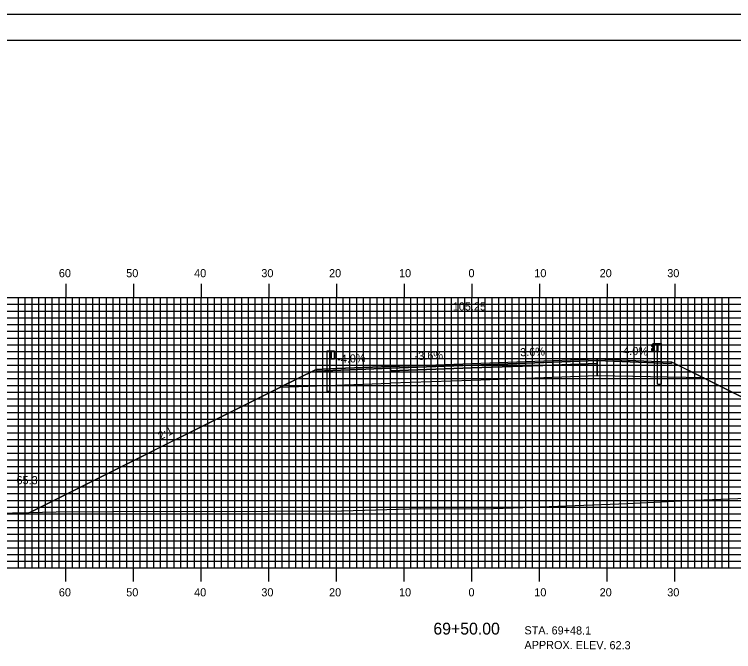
# Model space of a CAD drawing. Extents: x 1759823 to 1760167, y 442591 to 442811.
# Drawn here: x 1759921.6 to 1760027.9, y 442716.3 to 442810.5 of the extents above; entities that cross this region are included whole.
import ezdxf

# ---------------------------------------------------------------- set-up
doc = ezdxf.new("R2010")
doc.units = 0
for name, color, linetype in [('ANNOTATION', 7, 'Continuous'), ('BORDER', 7, 'Continuous'), ('BORING - NO REFUSAL', 7, 'Continuous'), ('D_Guardrail_Beam_Lt', 7, 'Continuous'), ('D_Guardrail_Beam_Rt', 7, 'Continuous'), ('D_Roadway_Centerline', 7, 'Continuous'), ('D_Roadway_Centerline_Text', 7, 'Continuous'), ('D_Roadway_Edge_Shoulder', 7, 'Continuous'), ('D_Roadway_Edge_TW', 7, 'Continuous'), ('D_Roadway_Pavement', 7, 'Continuous'), ('D_Roadway_SlopeLines', 7, 'Continuous'), ('D_Roadway_SubGrade', 7, 'Continuous'), ('D_Text_Standard', 7, 'Continuous'), ('H_V ANNOTATION', 7, 'Continuous'), ('MAJOR', 7, 'Continuous'), ('MINOR', 7, 'Continuous'), ('PLOT BOUNDARY', 7, 'Continuous'), ('S_Roadway_Centerline', 7, 'Continuous')]:
    doc.layers.add(name, color=color, linetype=linetype)

msp = doc.modelspace()

# ---------------------------------------------------------------- linework, layer by layer
at = {"layer": 'BORDER'}
msp.add_lwpolyline([(1759839.59, 442596.67), (1760159.59, 442596.67), (1760159.59, 442806.67), (1759839.59, 442806.67)], close=True, dxfattribs=at)
at = {"layer": 'D_Guardrail_Beam_Lt'}
for p, q in [((1759967.76, 442760.75), (1759967.76, 442754.75)), ((1759968.23, 442760.75), (1759967.76, 442760.75)), ((1759968.92, 442760.75), (1759968.23, 442760.75)), ((1759968.23, 442760.75), (1759968.23, 442759.58)), ((1759968.29, 442760.75), (1759968.29, 442759.58)), ((1759968.4, 442760.75), (1759968.4, 442759.58)), ((1759968.92, 442759.58), (1759968.92, 442760.75)), ((1759968.92, 442760.66), (1759968.99, 442760.65)), ((1759969.15, 442760.4), (1759968.95, 442760.26)), ((1759969.01, 442760.64), (1759969.15, 442760.54)), ((1759968.23, 442759.58), (1759968.92, 442759.58)), ((1759968.25, 442754.75), (1759968.25, 442759.58)), ((1759968.92, 442760.2), (1759968.92, 442760.13)), ((1759968.99, 442759.68), (1759968.92, 442759.66)), ((1759968.95, 442760.06), (1759969.15, 442759.93)), ((1759969.15, 442759.78), (1759969.01, 442759.68)), ((1759968.25, 442754.75), (1759967.76, 442754.75))]:
    msp.add_line(p, q, dxfattribs=at)
for centre, major_axis, start_param, end_param in [((1759968.98, 442760.61), (0.0417, 0), 0.959931, 1.376053), ((1759969.1, 442760.47), (0.0877, 0), 5.323254, 7.243116), ((1759969, 442760.2), (-0.0789, 0), 5.323254, 6.283185), ((1759969, 442760.13), (-0.0789, 0), 6.283185, 7.243116), ((1759968.98, 442759.72), (0.0417, 0), 4.907132, 5.323254), ((1759969.1, 442759.86), (0.0877, 0), 5.323254, 7.243116)]:
    msp.add_ellipse(centre, major_axis=major_axis, ratio=0.995501, start_param=start_param, end_param=end_param, dxfattribs=at)
at = {"layer": 'D_Guardrail_Beam_Rt'}
for p, q in [((1760015.92, 442761.74), (1760015.77, 442761.64)), ((1760015.77, 442761.5), (1760015.97, 442761.36)), ((1760016.01, 442761.76), (1760015.93, 442761.75)), ((1760016.01, 442761.85), (1760016.7, 442761.85)), ((1760016.01, 442760.68), (1760016.01, 442761.85)), ((1760016.53, 442761.85), (1760016.53, 442760.68)), ((1760016.63, 442761.85), (1760016.63, 442760.68)), ((1760016.7, 442761.85), (1760017.17, 442761.85)), ((1760016.7, 442761.85), (1760016.7, 442760.68)), ((1760017.17, 442761.85), (1760017.17, 442755.85)), ((1760015.97, 442761.16), (1760015.77, 442761.03)), ((1760015.77, 442760.88), (1760015.92, 442760.78)), ((1760015.93, 442760.78), (1760016.01, 442760.76)), ((1760016, 442761.3), (1760016, 442761.23)), ((1760016.7, 442760.68), (1760016.01, 442760.68)), ((1760016.67, 442755.85), (1760016.67, 442760.68)), ((1760016.67, 442755.85), (1760017.17, 442755.85))]:
    msp.add_line(p, q, dxfattribs=at)
for centre, major_axis, start_param, end_param in [((1760015.83, 442761.57), (-0.0877, 0), 5.323254, 7.243116), ((1760015.94, 442761.71), (-0.0417, 0), 4.907132, 5.323254), ((1760015.83, 442760.95), (-0.0877, 0), 5.323254, 7.243116), ((1760015.94, 442760.82), (-0.0417, 0), 0.959931, 1.376053), ((1760015.92, 442761.3), (0.0789, 0), 0, 0.959931), ((1760015.92, 442761.23), (0.0789, 0), 5.323254, 6.283185)]:
    msp.add_ellipse(centre, major_axis=major_axis, ratio=0.995501, start_param=start_param, end_param=end_param, dxfattribs=at)
at = {"layer": 'D_Roadway_Centerline'}
msp.add_lwpolyline([(1759923.86, 442736.88), (1759960.89, 442755.4), (1759966.19, 442758.04), (1759969.19, 442758.16), (1759977.19, 442758.48), (1759989.19, 442758.91), (1760001.19, 442759.35), (1760007.74, 442759.58), (1760015.74, 442759.26), (1760018.74, 442759.14), (1760023.49, 442756.77), (1760056.41, 442740.31)], dxfattribs=at)
at = {"layer": 'D_Roadway_Edge_Shoulder'}
for points in [[(1760007.74, 442759.58), (1760015.74, 442759.26), (1760015.74, 442759.26), (1760018.74, 442759.14), (1760018.74, 442758.89), (1760007.74, 442759.33)], [(1759977.19, 442758.48), (1759969.19, 442758.16), (1759969.19, 442758.16), (1759966.19, 442758.04), (1759966.19, 442757.79), (1759977.19, 442758.23)]]:
    msp.add_lwpolyline(points, close=True, dxfattribs=at)
at = {"layer": 'D_Roadway_Edge_TW'}
for points in [[(1759977.19, 442758.23), (1759977.19, 442758.48), (1759989.19, 442758.91), (1760001.19, 442759.35), (1760001.19, 442759.1), (1759989.19, 442758.66)], [(1760001.19, 442759.35), (1760007.74, 442759.58), (1760007.74, 442759.33), (1760001.19, 442759.1)]]:
    msp.add_lwpolyline(points, close=True, dxfattribs=at)
at = {"layer": 'D_Roadway_Pavement'}
for points in [[(1760001.19, 442759.1), (1760007.74, 442759.33), (1760007.74, 442758.92), (1760001.19, 442758.68)], [(1759977.19, 442757.82), (1759977.19, 442758.23), (1759989.19, 442758.66), (1760001.19, 442759.1), (1760001.19, 442758.68), (1759989.19, 442758.25)]]:
    msp.add_lwpolyline(points, close=True, dxfattribs=at)
for points in [[(1760007.74, 442759.33), (1760007.74, 442758.92)], [(1760007.74, 442759.33), (1760007.74, 442758.92)], [(1759977.19, 442758.23), (1759977.19, 442757.82)]]:
    msp.add_lwpolyline(points, dxfattribs=at)
at = {"layer": 'D_Roadway_SlopeLines'}
for points in [[(1760018.74, 442759.14), (1760056.41, 442740.31)], [(1759966.19, 442758.04), (1759923.86, 442736.88)]]:
    msp.add_lwpolyline(points, dxfattribs=at)
at = {"layer": 'D_Roadway_SubGrade'}
for points in [[(1760007.74, 442758.92), (1760007.74, 442759.33), (1760018.74, 442758.89), (1760018.74, 442759.14), (1760023.49, 442756.77), (1760007.74, 442757.08)], [(1759977.19, 442757.82), (1759977.19, 442758.23), (1759966.19, 442757.79), (1759966.19, 442758.04), (1759960.89, 442755.4), (1759977.19, 442755.98)], [(1759977.19, 442755.98), (1759977.19, 442757.82), (1759989.19, 442758.25), (1760001.19, 442758.68), (1760001.19, 442756.85), (1759989.19, 442756.41)], [(1760001.19, 442758.68), (1760007.74, 442758.92), (1760007.74, 442757.08), (1760001.19, 442756.85)]]:
    msp.add_lwpolyline(points, close=True, dxfattribs=at)
at = {"layer": 'MAJOR'}
for p, q in [((1759929.19, 442770.67), (1759929.19, 442768.67)), ((1759939.19, 442770.67), (1759939.19, 442768.67)), ((1759949.19, 442770.67), (1759949.19, 442768.67)), ((1759959.19, 442770.67), (1759959.19, 442768.67)), ((1759969.19, 442770.67), (1759969.19, 442768.67)), ((1759979.19, 442770.67), (1759979.19, 442768.67)), ((1759989.19, 442770.67), (1759989.19, 442768.67)), ((1759999.19, 442770.67), (1759999.19, 442768.67)), ((1760009.19, 442770.67), (1760009.19, 442768.67)), ((1760019.19, 442770.67), (1760019.19, 442768.67)), ((1759849.19, 442768.67), (1760129.19, 442768.67)), ((1759849.19, 442768.67), (1760129.19, 442768.67)), ((1759929.19, 442728.67), (1759929.19, 442768.67)), ((1759939.19, 442728.67), (1759939.19, 442768.67)), ((1759949.19, 442728.67), (1759949.19, 442768.67)), ((1759959.19, 442728.67), (1759959.19, 442768.67)), ((1759969.19, 442728.67), (1759969.19, 442768.67)), ((1759979.19, 442728.67), (1759979.19, 442768.67)), ((1759989.19, 442728.67), (1759989.19, 442768.67)), ((1759999.19, 442728.67), (1759999.19, 442768.67)), ((1760009.19, 442728.67), (1760009.19, 442768.67)), ((1760019.19, 442728.67), (1760019.19, 442768.67)), ((1759849.19, 442763.67), (1760129.19, 442763.67)), ((1759849.19, 442758.67), (1760129.19, 442758.67)), ((1759849.19, 442753.67), (1760129.19, 442753.67)), ((1759849.19, 442748.67), (1760129.19, 442748.67)), ((1759849.19, 442743.67), (1760129.19, 442743.67)), ((1759849.19, 442738.67), (1760129.19, 442738.67)), ((1759849.19, 442733.67), (1760129.19, 442733.67)), ((1759849.19, 442728.67), (1760129.19, 442728.67)), ((1759849.19, 442728.67), (1760129.19, 442728.67)), ((1759929.19, 442726.66), (1759929.19, 442728.67)), ((1759939.19, 442726.66), (1759939.19, 442728.67)), ((1759949.19, 442726.66), (1759949.19, 442728.67)), ((1759959.19, 442726.66), (1759959.19, 442728.67)), ((1759969.19, 442726.66), (1759969.19, 442728.67)), ((1759979.19, 442726.66), (1759979.19, 442728.67)), ((1759989.19, 442726.66), (1759989.19, 442728.67)), ((1759999.19, 442726.66), (1759999.19, 442728.67)), ((1760009.19, 442726.66), (1760009.19, 442728.67)), ((1760019.19, 442726.66), (1760019.19, 442728.67))]:
    msp.add_line(p, q, dxfattribs=at)
at = {"layer": 'MINOR'}
for p, q in [((1759922.19, 442728.67), (1759922.19, 442768.67)), ((1759923.19, 442728.67), (1759923.19, 442768.67)), ((1759924.19, 442728.67), (1759924.19, 442768.67)), ((1759925.19, 442728.67), (1759925.19, 442768.67)), ((1759926.19, 442728.67), (1759926.19, 442768.67)), ((1759927.19, 442728.67), (1759927.19, 442768.67)), ((1759928.19, 442728.67), (1759928.19, 442768.67)), ((1759930.19, 442728.67), (1759930.19, 442768.67)), ((1759931.19, 442728.67), (1759931.19, 442768.67)), ((1759932.19, 442728.67), (1759932.19, 442768.67)), ((1759933.19, 442728.67), (1759933.19, 442768.67)), ((1759934.19, 442728.67), (1759934.19, 442768.67)), ((1759935.19, 442728.67), (1759935.19, 442768.67)), ((1759936.19, 442728.67), (1759936.19, 442768.67)), ((1759937.19, 442728.67), (1759937.19, 442768.67)), ((1759938.19, 442728.67), (1759938.19, 442768.67)), ((1759940.19, 442728.67), (1759940.19, 442768.67)), ((1759941.19, 442728.67), (1759941.19, 442768.67)), ((1759942.19, 442728.67), (1759942.19, 442768.67)), ((1759943.19, 442728.67), (1759943.19, 442768.67)), ((1759944.19, 442728.67), (1759944.19, 442768.67)), ((1759945.19, 442728.67), (1759945.19, 442768.67)), ((1759946.19, 442728.67), (1759946.19, 442768.67)), ((1759947.19, 442728.67), (1759947.19, 442768.67)), ((1759948.19, 442728.67), (1759948.19, 442768.67)), ((1759950.19, 442728.67), (1759950.19, 442768.67)), ((1759951.19, 442728.67), (1759951.19, 442768.67)), ((1759952.19, 442728.67), (1759952.19, 442768.67)), ((1759953.19, 442728.67), (1759953.19, 442768.67)), ((1759954.19, 442728.67), (1759954.19, 442768.67)), ((1759955.19, 442728.67), (1759955.19, 442768.67)), ((1759956.19, 442728.67), (1759956.19, 442768.67)), ((1759957.19, 442728.67), (1759957.19, 442768.67)), ((1759958.19, 442728.67), (1759958.19, 442768.67)), ((1759960.19, 442728.67), (1759960.19, 442768.67)), ((1759961.19, 442728.67), (1759961.19, 442768.67)), ((1759962.19, 442728.67), (1759962.19, 442768.67)), ((1759963.19, 442728.67), (1759963.19, 442768.67)), ((1759964.19, 442728.67), (1759964.19, 442768.67)), ((1759965.19, 442728.67), (1759965.19, 442768.67)), ((1759966.19, 442728.67), (1759966.19, 442768.67)), ((1759967.19, 442728.67), (1759967.19, 442768.67)), ((1759968.19, 442728.67), (1759968.19, 442768.67)), ((1759970.19, 442728.67), (1759970.19, 442768.67)), ((1759971.19, 442728.67), (1759971.19, 442768.67)), ((1759972.19, 442728.67), (1759972.19, 442768.67)), ((1759973.19, 442728.67), (1759973.19, 442768.67)), ((1759974.19, 442728.67), (1759974.19, 442768.67)), ((1759975.19, 442728.67), (1759975.19, 442768.67)), ((1759976.19, 442728.67), (1759976.19, 442768.67)), ((1759977.19, 442728.67), (1759977.19, 442768.67)), ((1759978.19, 442728.67), (1759978.19, 442768.67)), ((1759980.19, 442728.67), (1759980.19, 442768.67)), ((1759981.19, 442728.67), (1759981.19, 442768.67)), ((1759982.19, 442728.67), (1759982.19, 442768.67)), ((1759983.19, 442728.67), (1759983.19, 442768.67)), ((1759984.19, 442728.67), (1759984.19, 442768.67)), ((1759985.19, 442728.67), (1759985.19, 442768.67)), ((1759986.19, 442728.67), (1759986.19, 442768.67)), ((1759987.19, 442728.67), (1759987.19, 442768.67)), ((1759988.19, 442728.67), (1759988.19, 442768.67)), ((1759990.19, 442728.67), (1759990.19, 442768.67)), ((1759991.19, 442728.67), (1759991.19, 442768.67)), ((1759992.19, 442728.67), (1759992.19, 442768.67)), ((1759993.19, 442728.67), (1759993.19, 442768.67)), ((1759994.19, 442728.67), (1759994.19, 442768.67)), ((1759995.19, 442728.67), (1759995.19, 442768.67)), ((1759996.19, 442728.67), (1759996.19, 442768.67)), ((1759997.19, 442728.67), (1759997.19, 442768.67)), ((1759998.19, 442728.67), (1759998.19, 442768.67)), ((1760000.19, 442728.67), (1760000.19, 442768.67)), ((1760001.19, 442728.67), (1760001.19, 442768.67)), ((1760002.19, 442728.67), (1760002.19, 442768.67)), ((1760003.19, 442728.67), (1760003.19, 442768.67)), ((1760004.19, 442728.67), (1760004.19, 442768.67)), ((1760005.19, 442728.67), (1760005.19, 442768.67)), ((1760006.19, 442728.67), (1760006.19, 442768.67)), ((1760007.19, 442728.67), (1760007.19, 442768.67)), ((1760008.19, 442728.67), (1760008.19, 442768.67)), ((1760010.19, 442728.67), (1760010.19, 442768.67)), ((1760011.19, 442728.67), (1760011.19, 442768.67)), ((1760012.19, 442728.67), (1760012.19, 442768.67)), ((1760013.19, 442728.67), (1760013.19, 442768.67)), ((1760014.19, 442728.67), (1760014.19, 442768.67)), ((1760015.19, 442728.67), (1760015.19, 442768.67)), ((1760016.19, 442728.67), (1760016.19, 442768.67)), ((1760017.19, 442728.67), (1760017.19, 442768.67)), ((1760018.19, 442728.67), (1760018.19, 442768.67)), ((1760020.19, 442728.67), (1760020.19, 442768.67)), ((1760021.19, 442728.67), (1760021.19, 442768.67)), ((1760022.19, 442728.67), (1760022.19, 442768.67)), ((1760023.19, 442728.67), (1760023.19, 442768.67)), ((1760024.19, 442728.67), (1760024.19, 442768.67)), ((1760025.19, 442728.67), (1760025.19, 442768.67)), ((1760026.19, 442728.67), (1760026.19, 442768.67)), ((1760027.19, 442728.67), (1760027.19, 442768.67)), ((1759849.19, 442767.67), (1760129.19, 442767.67)), ((1759849.19, 442766.67), (1760129.19, 442766.67)), ((1759849.19, 442765.67), (1760129.19, 442765.67)), ((1759849.19, 442764.67), (1760129.19, 442764.67)), ((1759849.19, 442762.67), (1760129.19, 442762.67)), ((1759849.19, 442761.67), (1760129.19, 442761.67)), ((1759849.19, 442760.67), (1760129.19, 442760.67)), ((1759849.19, 442759.67), (1760129.19, 442759.67)), ((1759849.19, 442757.67), (1760129.19, 442757.67)), ((1759849.19, 442756.67), (1760129.19, 442756.67)), ((1759849.19, 442755.67), (1760129.19, 442755.67)), ((1759849.19, 442754.67), (1760129.19, 442754.67)), ((1759849.19, 442752.67), (1760129.19, 442752.67)), ((1759849.19, 442751.67), (1760129.19, 442751.67)), ((1759849.19, 442750.67), (1760129.19, 442750.67)), ((1759849.19, 442749.67), (1760129.19, 442749.67)), ((1759849.19, 442747.67), (1760129.19, 442747.67)), ((1759849.19, 442746.67), (1760129.19, 442746.67)), ((1759849.19, 442745.67), (1760129.19, 442745.67)), ((1759849.19, 442744.67), (1760129.19, 442744.67)), ((1759849.19, 442742.67), (1760129.19, 442742.67)), ((1759849.19, 442741.67), (1760129.19, 442741.67)), ((1759849.19, 442740.67), (1760129.19, 442740.67)), ((1759849.19, 442739.67), (1760129.19, 442739.67)), ((1759849.19, 442737.67), (1760129.19, 442737.67)), ((1759849.19, 442736.67), (1760129.19, 442736.67)), ((1759849.19, 442735.67), (1760129.19, 442735.67)), ((1759849.19, 442734.67), (1760129.19, 442734.67)), ((1759849.19, 442732.67), (1760129.19, 442732.67)), ((1759849.19, 442731.67), (1760129.19, 442731.67)), ((1759849.19, 442730.67), (1760129.19, 442730.67)), ((1759849.19, 442729.67), (1760129.19, 442729.67))]:
    msp.add_line(p, q, dxfattribs=at)
at = {"layer": 'PLOT BOUNDARY'}
msp.add_lwpolyline([(1759823.4, 442590.55), (1760163.4, 442590.55), (1760163.4, 442810.55), (1759823.4, 442810.55)], close=True, dxfattribs=at)
at = {"layer": 'S_Roadway_Centerline'}
msp.add_lwpolyline([(1759849.19, 442735.32), (1759856.26, 442735.23), (1759864.27, 442735.11), (1759866.18, 442735.16), (1759884.93, 442735.84), (1759888.48, 442735.9), (1759892.58, 442735.99), (1759905.99, 442736.42), (1759911.62, 442736.59), (1759918.83, 442736.79), (1759923.72, 442736.88), (1759927.75, 442736.96), (1759944.69, 442737.06), (1759948.49, 442737.03), (1759969.96, 442737.1), (1759969.97, 442737.1), (1759969.97, 442737.1), (1759981.65, 442737.46), (1759990.98, 442737.4), (1759996.73, 442737.6), (1760012.19, 442738.19), (1760022.28, 442738.7), (1760033.54, 442739.13)], dxfattribs=at)

# ---------------------------------------------------------------- texts
at = {"layer": 'ANNOTATION'}
for s, rotation, p in [('-4.0%', 357.7094, (1760011.03, 442760.25)), ('-3.6%', 2.0618, (1759980.77, 442759.41)), ('3.6%', 2.0618, (1759996.37, 442759.97)), ('-4.0%', 2.2906, (1759969.32, 442758.97)), ('2:1', 26.5651, (1759943.17, 442747.57))]:
    msp.add_text(s, height=1.2, rotation=rotation, dxfattribs=at).set_placement(p)
at = {"layer": 'BORING - NO REFUSAL'}
for s, p in [('STA. 69+48.1', (1759996.98, 442718.85)), ('APPROX. ELEV. 62.3', (1759996.98, 442716.69))]:
    msp.add_text(s, height=1.2, rotation=359.8142, dxfattribs=at).set_placement(p)
at = {"layer": 'D_Roadway_Centerline'}
for s, p in [('C', (1759989.18, 442758.91)), ('L', (1759989.19, 442758.91))]:
    msp.add_text(s, height=0.0146, dxfattribs=at).set_placement(p)
at = {"layer": 'D_Roadway_Centerline_Text'}
msp.add_text('105.25', height=1.2, dxfattribs=at).set_placement((1759986.39, 442766.75))
at = {"layer": 'D_Text_Standard'}
msp.add_text("65.3'", height=1.2, dxfattribs=at).set_placement((1759921.9, 442741.06))
at = {"layer": 'H_V ANNOTATION'}
for s, height, p in [('60', 1.2, (1759928.16, 442771.67)), ('50', 1.2, (1759938.12, 442771.67)), ('40', 1.2, (1759948.16, 442771.67)), ('30', 1.2, (1759958.09, 442771.67)), ('20', 1.2, (1759968.1, 442771.67)), ('10', 1.2, (1759978.44, 442771.67)), ('0', 1.2, (1759988.71, 442771.67)), ('10', 1.2, (1759998.44, 442771.67)), ('20', 1.2, (1760008.1, 442771.67)), ('30', 1.2, (1760018.09, 442771.67)), ('60', 1.2, (1759928.16, 442724.47)), ('50', 1.2, (1759938.12, 442724.47)), ('40', 1.2, (1759948.16, 442724.47)), ('30', 1.2, (1759958.09, 442724.47)), ('20', 1.2, (1759968.1, 442724.47)), ('10', 1.2, (1759978.44, 442724.47)), ('0', 1.2, (1759988.71, 442724.47)), ('10', 1.2, (1759998.44, 442724.47)), ('20', 1.2, (1760008.1, 442724.47)), ('30', 1.2, (1760018.09, 442724.47)), ('69+50.00', 1.75, (1759983.52, 442718.82))]:
    msp.add_text(s, height=height, dxfattribs=at).set_placement(p)

doc.saveas('drawing.dxf')
